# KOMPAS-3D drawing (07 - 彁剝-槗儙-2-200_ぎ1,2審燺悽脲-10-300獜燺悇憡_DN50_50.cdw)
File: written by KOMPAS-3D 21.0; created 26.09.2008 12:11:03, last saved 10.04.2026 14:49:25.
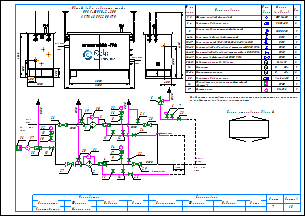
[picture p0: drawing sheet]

Sheets 1-2: A3, landscape

Document properties: Наименование: Макро:21; Автор: RaskoAdmin; Форматы листов документа: 2xA3; Полное имя файла: \\UR38nt01\Departments\КТО\КБ ПУРДГ\Заявки\Прайс-лист на типовые шкафы ГРПШ\ПРДГ_стандарт_20_03_2026\ПРДГ с РДСК\ПРДГ-ШУГО-2-200_до1,2МПа_Рвых-10-300кПа_РДСК_DN50_50.cdw

Title block, sheet 1: Наименование: Пункт учета газа / ПУГ-Ш-400-Р / ЛГТИ.485922.001ТУ; designation: ЛГТИ.03.4411141; sheet number: 1; Количество листов документа: 2; organisation: ООО "ЭЛЬСТЕР Газэлектроника"; Форматы листов документа: A3; stored path: C:\Рабочие документы\Компас\ПУГ\Схема.cdw; Разработал: Устинов; Проверил: Кошкин; Утвердил: Кошкин
Title block, sheet 2: sheet number: 2; stored path: D:\Рабочие документы\Заявки\ПУРДГ\ПУРДГ-ШУЭО-2-100-Р 4411220.cdw; designation, second copy: ЛГТИ.03.4411141-

Views: Вид 1, Вид 2
Referenced files: wcvoit.frw
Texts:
  Normal
  Вход
  газа
  PDI
  Выход
  Р=     кПа
  DN50
  DN20
  Импульс DN20
  ≥5DN
  HYSWLongFangSong
  № на
  схеме
  Усл.
  обозн.
  Марка
  (модель)
  Кол.
  Фильтр газовый фланцевый
  ФГ 16-50
  Регулятор давления газа
  РДCК-50
  Клапан предохранительный сбросной
  КПС DN20
  Кран шаровой газовый латунный
  DN15
  Кран кнопочный VE-РАСКО-НЗ-1,6-G1/2-М20
  Кран шаровой "под приварку" штуцерный DN20 PN16
  Кран шаровой "под приварку" штуцерный п/п DN20 PN16
  Кран шаровой фланцевый DN50 PN16
  Индикатор перепада давления
  Delta 15
  Манометр
  Манометр-напоромер
  0...     МПа
  0...     кПа
  Обогреватель газогорелочный шкафной
  (Эльтон")
  Счетчик газа
  Venio-A-15
  ОГШН
  BK-G1,6
  Общий вид и габариты шкафа
  ПРДГ-ШУГО-2-200
  Выход газа
  Вход газа
  Схема открывания дверей
  Р=       МПа
  logo-rasko-ge.png
  Предприятие изготовитель может заменять комплектующие на аналогичные,
  не ухудшающие заявленных характеристик.
  Должность
  Конструктор
  Фамилия
  Подпись
  Дата
  Согласовано
  Максимкин
  Лист
  Листов
  POLYLINE_STYLE_0.18_RGB_0_0_0
  POLYLINE_STYLE_0.50_RGB_0_0_0
  POLYLINE_STYLE_0.34_RGB_0_0_0
  PHANTOM_RGB_0_0_0_SC_1_THICK_0.18
  K5LT_THIN_RGB_0_0_0_THICK_0.18
  K5LT32769_RGB_0_0_0_THICK_0.18
  K5LT12_RGB_0_0_0_SC_1_THICK_0.18
  K5LT_DASHED_RGB_0_0_0_SC_1_THICK_0.18
  ACISOTGL_RGB_0_0_0_SC_0.8_THICK_0.25
  CONTINUOUS_RGB_0_127_31_THICK_0.3
  CONTINUOUS_RGB_0_0_255_THICK_0.35
  CONTINUOUS_RGB_255_0_0_THICK_0.35
  POLYLINE_STYLE_0.25_RGB_0_0_0
  CONTINUOUS_RGB_0_0_0_THICK_0.5
  POLYLINE_STYLE_0.35_RGB_0_0_255
  CONTINUOUS_RGB_0_0_0_THICK_0.4
  CONTINUOUS_RGB_0_0_0_THICK_0.35
  Без оформления
Dimensions and other numbers on the sheet: 1; 2; 3; 4; 5; 10; 27; 28; 29; 23; 8; 12; 18; 19; 20; 21; 22; 25; 24; 30; 31; 15; 16; 35; 36; 26; 6; 7; 11; 14; 13; 33; 1, 2; 3, 4; 6-14; 9; 15-17; 18-23; 24-25; 26-29; 30-31; 32; 33-34; 37; 1000; 400; 1050; 500; 305; 2000; 4130; 1565; 2300; 17; 34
